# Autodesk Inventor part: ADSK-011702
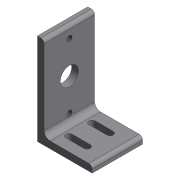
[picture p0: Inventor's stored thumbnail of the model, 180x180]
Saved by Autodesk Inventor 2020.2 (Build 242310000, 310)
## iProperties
Created: 2000-03
Part Number: ADSK-011702
Material: Pearson HRS
Document SubType Name: Modeling
Designer: sspink
Density: 7.83 g/cm^3
Appearance: Métal - Acier
Mass: 925.825 g
Surface Area: 319.761 cm^2
Volume: 118.241 cm^3
Control State: 0
Master: False
Checked Out: False
Shininess: 0.0
Length Units: 11269
Angle Units: 11279
Time Units: 11290
Mass Units: 11283
Length Display Precision: 3
Angle Display Precision: 2
Compacted: True
Cutlength: 3.0
Material Desc: ANGLE,HRS,.375X5.00X3.00
Material_Number: A084096
Dimensions: 127x70x76,2 mm
Mass: 0,926 kg
VLT_Material: Pearson HRS
Density: 0.0
Volumn: 0.0
Area: 0.0
PropertySet Name: Model Information
Author: sspink
Revision Number: -
Title: ADSK-011702
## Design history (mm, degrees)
node "Extrusion1" dims "d9" = 0, "Length" = 70
node "Hole1" dims "d14" = 7.7978, "d15" = 9.525, "d16" = 6.35, "d17" = 60 deg, "d18" = 19.05, "d19" = 118 deg
  sketch "Sketch3"
    geometry: L1 (0, 104.458)-(-70, 104.458) reference; L2 (-35, 93.22)-(-35, 3.22); L3 (0, 109.22)-(-70, 109.22) reference; 1 further point
    constraints: 2 end point, 1 midpoint, 1 vertical, 1 vertical alignment
    dimensions: "d37" = 90 distance of L2.start L2.end; "d38" = 16 distance from line of L3 L2.start
node "Extrusion2" dims "d24" = 25.4, "d25" = 0
  sketch "Sketch4"
    geometry: L1 (25, 14.5)-(50, 14.5); L2 (50, 14.5)-(50, 23.5); L3 (50, 23.5)-(25, 23.5); L4 (25, 23.5)-(25, 14.5); L5 (0, 0)-(0, 70) reference; L6 (25, 19)-(50, 19); L7 (0, 35)-(76.2, 35); A1 r 4.5 centre (25, 19) between (25, 23.5) and (25, 14.5); A2 r 4.5 centre (50, 19) between (50, 14.5) and (50, 23.5); 1 further point
    constraints: 12 end point, 4 point on circle, 3 horizontal, 2 centre point, 2 parallel, 2 tangent, 1 midpoint, 1 perpendicular, 1 vertical alignment
    dimensions: "d20" = 9 distance between parallel lines of L3 L1; "d21" = 25 distance of L6.end L6.start; "d36" = 25 distance from line of L6.start L5; "d41" = 16 distance between parallel lines of L6 L7
node "Hole2" dims "d29" = 25.4, "d30" = 9.525, "d31" = 6.35, "d32" = 60 deg, "d33" = 19.05, "d34" = 118 deg
mirror "Spiegeln1"
node "Solide1"
node "Corps solides"
node "Corps surfaciques"
sketch "Sketch2"
  geometry: L1 (32.408, 38.758)-(108.608, 38.758); L2 (32.408, 165.758)-(32.408, 38.758); L3 (41.933, 160.995)-(41.933, 56.538); L4 (50.188, 48.283)-(103.845, 48.283); L5 (32.408, 165.758)-(37.17, 165.758); L6 (108.608, 43.52)-(108.608, 38.758); A1 r 4.763 centre (37.17, 160.995) between (41.933, 160.995) and (37.17, 165.758); A2 r 4.763 centre (103.845, 43.52) between (108.608, 43.52) and (103.845, 48.283); A3 r 8.255 centre (50.188, 56.538) between (41.933, 56.538) and (50.188, 48.283); 1 further point
  constraints: 12 end point, 6 point on circle, 6 tangent, 3 centre point, 1 coincident, 1 equal radius, 1 horizontal, 1 perpendicular, 1 other
  dimensions: "d0" = 9.525 distance between parallel lines of L2 L3 (= Thickness); "d6" = 4.7625 radius of A1 (= 0.5 x Thickness); "d7" = 8.255 radius of A3 (computed from Thickness); "d2" = 127 distance between parallel lines of L1 L5 (= Vertical_Length); "d4" = 76.2 distance between parallel lines of L6 L2 (= Horizontal_length)
sketch "Sketch5"
  geometry: L1 (0, 0)-(70, 0) reference; L2 (35, 21)-(35, 111); C1 r 3.899 at (35, 111) reference; C2 r 3.899 at (35, 21) reference; 1 further point
  constraints: 2 end point, 1 midpoint, 1 perpendicular
other parameters: "Thickness" = 9.525, "Vertical_Length" = 127, "Horizontal_length" = 76.2
